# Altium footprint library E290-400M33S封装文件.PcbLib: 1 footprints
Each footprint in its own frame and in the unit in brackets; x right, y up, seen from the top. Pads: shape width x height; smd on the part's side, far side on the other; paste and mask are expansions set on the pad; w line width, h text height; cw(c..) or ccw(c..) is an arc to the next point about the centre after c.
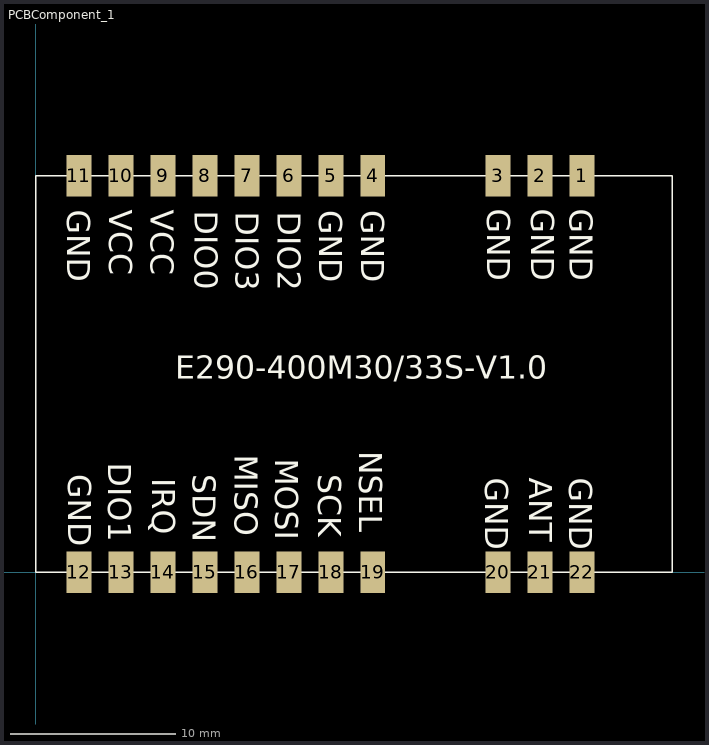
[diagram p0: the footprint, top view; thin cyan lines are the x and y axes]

## PCBComponent_1 [mm]
pads (22):
  rect 1.5x2.5 smd: 1(33.04,24) 2(30.5,24) 3(27.96,24) 4(20.39,24) 5(17.85,24) 6(15.31,24) 7(12.77,24) 8(10.23,24) 9(7.69,24) 10(5.15,24) 11(2.61,24) 12(2.61,0) 13(5.15,0) 14(7.69,0) 15(10.23,0) 16(12.77,0) 17(15.31,0) 18(17.85,0) 19(20.39,0) 20(27.96,0) 21(30.5,0) 22(33.04,0)
Top Overlay:
  lines w0.1: 0,0 0,24 38.5,24 38.5,0 0,0
  text "NSEL" at 19.562,7.336 h1.4
  text "SCK" at 17.097,5.936 h1.4
  text "MOSI" at 14.497,6.869 h1.4
  text "MISO" at 12.032,7.102 h1.4
  text "SDN" at 9.507,5.936 h1.4
  text "IRQ" at 7.042,5.703 h1.4
  text "DIO1" at 4.381,6.636 h1.4
  text "GND" at 1.961,5.936 h1.4
  text "GND" at 27.196,5.709 h1.4
  text "ANT" at 29.838,5.709 h1.4
  text "GND" at 32.265,5.709 h1.4
  text "GND" at 32.292,22.009 h1.4
  text "GND" at 29.97,22.009 h1.4
  text "GND" at 27.297,22.009 h1.4
  text "GND" at 1.897,21.949 h1.4
  text "VCC" at 4.43,21.949 h1.4
  text "VCC" at 6.964,21.949 h1.4
  text "DIO0" at 9.602,21.883 h1.4
  text "DIO3" at 12.105,21.831 h1.4
  text "DIO2" at 14.638,21.831 h1.4
  text "GND" at 17.141,21.904 h1.4
  text "GND" at 19.674,21.904 h1.4
  text "E290-400M30/33S-V1.0" at 8.441,11.722 h1.4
